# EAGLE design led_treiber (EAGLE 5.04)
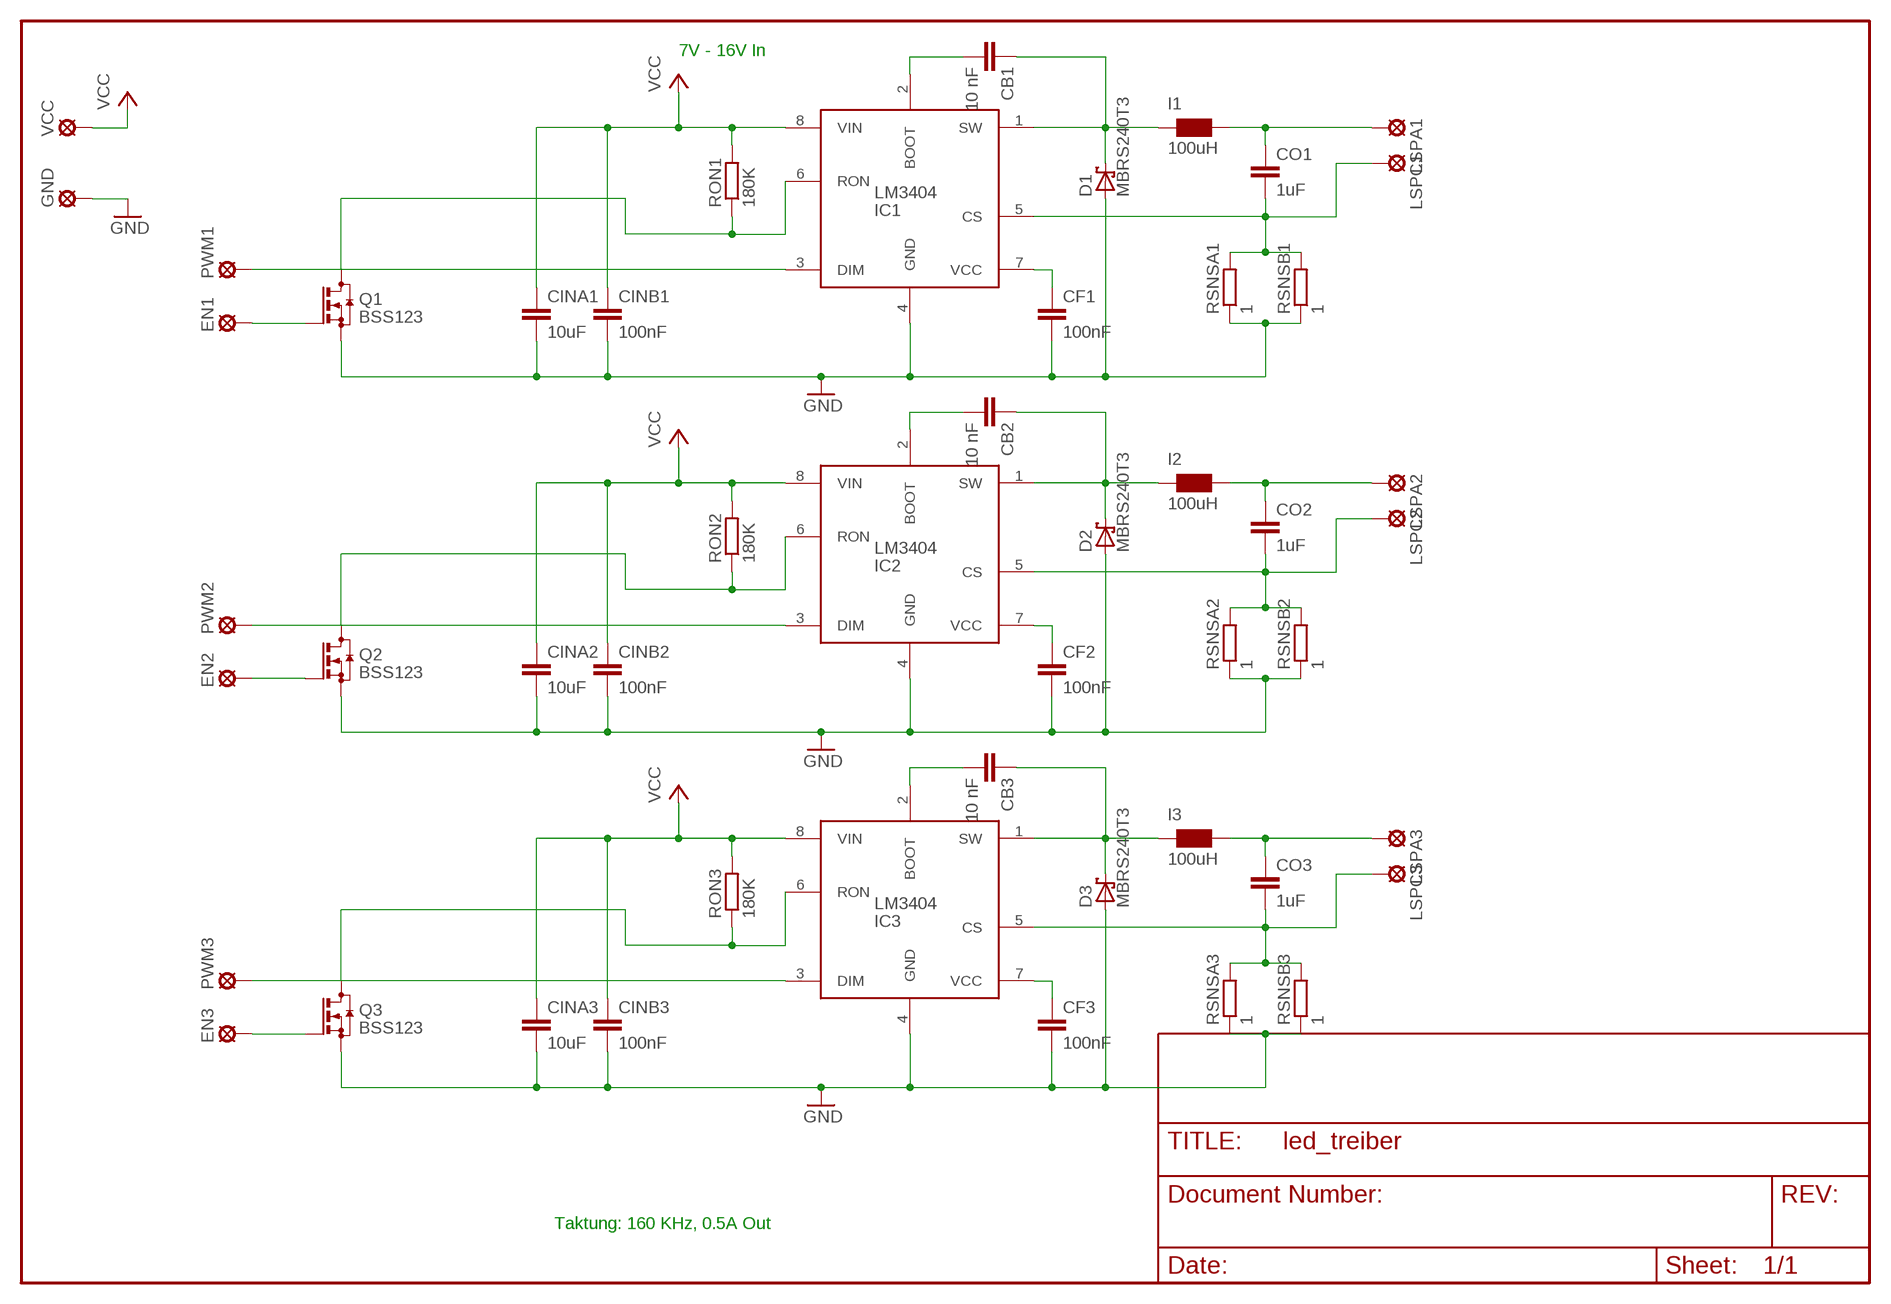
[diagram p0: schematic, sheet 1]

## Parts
CB1  10 nF  C-EUC0805  [C0805]
CB2  10 nF  C-EUC0805  [C0805]
CB3  10 nF  C-EUC0805  [C0805]
CF1  100nF  C-EUC0805  [C0805]
CF2  100nF  C-EUC0805  [C0805]
CF3  100nF  C-EUC0805  [C0805]
CINA1  10uF  C-EUC1210  [C1210]
CINA2  10uF  C-EUC1210  [C1210]
CINA3  10uF  C-EUC1210  [C1210]
CINB1  100nF  C-EUC0805  [C0805]
CINB2  100nF  C-EUC0805  [C0805]
CINB3  100nF  C-EUC0805  [C0805]
CO1  1uF  C-EUC1210  [C1210]
CO2  1uF  C-EUC1210  [C1210]
CO3  1uF  C-EUC1210  [C1210]
D1  MBRS240T3  MBRS130LT3  [SMB]
D2  MBRS240T3  MBRS130LT3  [SMB]
D3  MBRS240T3  MBRS130LT3  [SMB]
EN1  LSP10  [LSP10]
EN2  LSP10  [LSP10]
EN3  LSP10  [LSP10]
GND  LSP10  [LSP10]
I1  100uH  WE-PD_L/XL/XXL  [WE-PD_L/XL/XXL]
I2  100uH  WE-PD_L/XL/XXL  [WE-PD_L/XL/XXL]
I3  100uH  WE-PD_L/XL/XXL  [WE-PD_L/XL/XXL]
IC1  LM3404  [SO-8]
IC2  LM3404  [SO-8]
IC3  LM3404  [SO-8]
LSPA1  LSP10  [LSP10]
LSPA2  LSP10  [LSP10]
LSPA3  LSP10  [LSP10]
LSPC1  LSP10  [LSP10]
LSPC2  LSP10  [LSP10]
LSPC3  LSP10  [LSP10]
PWM1  LSP10  [LSP10]
PWM2  LSP10  [LSP10]
PWM3  LSP10  [LSP10]
Q1  BSS123  [SOT23]
Q2  BSS123  [SOT23]
Q3  BSS123  [SOT23]
RON1  180K  R-EU_R0805  [R0805]
RON2  180K  R-EU_R0805  [R0805]
RON3  180K  R-EU_R0805  [R0805]
RSNSA1  1  R-EU_R0805  [R0805]
RSNSA2  1  R-EU_R0805  [R0805]
RSNSA3  1  R-EU_R0805  [R0805]
RSNSB1  1  R-EU_R0805  [R0805]
RSNSB2  1  R-EU_R0805  [R0805]
RSNSB3  1  R-EU_R0805  [R0805]
VCC  LSP10  [LSP10]

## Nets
ANODE1: CO1.1 I1.1 LSPA1.MP
ANODE2: CO2.1 I2.1 LSPA2.MP
ANODE3: CO3.1 I3.1 LSPA3.MP
BOOT1: CB1.2 IC1.2(BOOT)
BOOT2: CB2.2 IC2.2(BOOT)
BOOT3: CB3.2 IC3.2(BOOT)
CATHODE1: CO1.2 IC1.5(CS) LSPC1.MP RSNSA1.2 RSNSB1.2
CATHODE2: CO2.2 IC2.5(CS) LSPC2.MP RSNSA2.2 RSNSB2.2
CATHODE3: CO3.2 IC3.5(CS) LSPC3.MP RSNSA3.2 RSNSB3.2
CF1: CF1.1 IC1.7(VCC)
CF2: CF2.1 IC2.7(VCC)
CF3: CF3.1 IC3.7(VCC)
ENABLE1: IC1.6(RON) Q1.3(D) RON1.1
ENABLE2: IC2.6(RON) Q2.3(D) RON2.1
ENABLE3: IC3.6(RON) Q3.3(D) RON3.1
ENABLEOUT1: EN1.MP Q1.1(G)
ENABLEOUT2: EN2.MP Q2.1(G)
ENABLEOUT3: EN3.MP Q3.1(G)
GND: CF1.2 CF2.2 CF3.2 CINA1.2 CINA2.2 CINA3.2 CINB1.2 CINB2.2 CINB3.2 D1.A D2.A D3.A GND.MP IC1.4(GND) IC2.4(GND) IC3.4(GND) Q1.2(S) Q2.2(S) Q3.2(S) RSNSA1.1 RSNSA2.1 RSNSA3.1 RSNSB1.1 RSNSB2.1 RSNSB3.1
PWM1: IC1.3(DIM) PWM1.MP
PWM2: IC2.3(DIM) PWM2.MP
PWM3: IC3.3(DIM) PWM3.MP
SW1: CB1.1 D1.C I1.2 IC1.1(SW)
SW2: CB2.1 D2.C I2.2 IC2.1(SW)
SW3: CB3.1 D3.C I3.2 IC3.1(SW)
VCC: CINA1.1 CINA2.1 CINA3.1 CINB1.1 CINB2.1 CINB3.1 IC1.8(VIN) IC2.8(VIN) IC3.8(VIN) RON1.2 RON2.2 RON3.2 VCC.MP

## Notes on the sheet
- 7V - 16V In
- Taktung: 160 KHz, 0.5A Out

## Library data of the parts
CB1-CB3 CF1-CF3 CINA1-CINA3 CINB1-CINB3 CO1-CO3 = rcl:C-EU: CAPACITOR, European symbol
D1-D3 = diode:MBRS130LT3: Schottky Power Rectifier
EN1-EN3 GND LSPA1-LSPA3 LSPC1-LSPC3 PWM1-PWM3 VCC = solpad:LSP10: SOLDER PAD
I1-I3 = wuerth-elektronik:WE-PD: SMD-Shielded Power Inductors WE-PD
IC1-IC3 = lm3404:LM3404
Q1-Q3 = transistor-small-signal:BSS123: N-CHANNEL MOS FET
RON1-RON3 RSNSA1-RSNSA3 RSNSB1-RSNSB3 = rcl:R-EU_: RESISTOR, European symbol

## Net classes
0 default: width 0.635 mm
1 vcc: width 0.254 mm

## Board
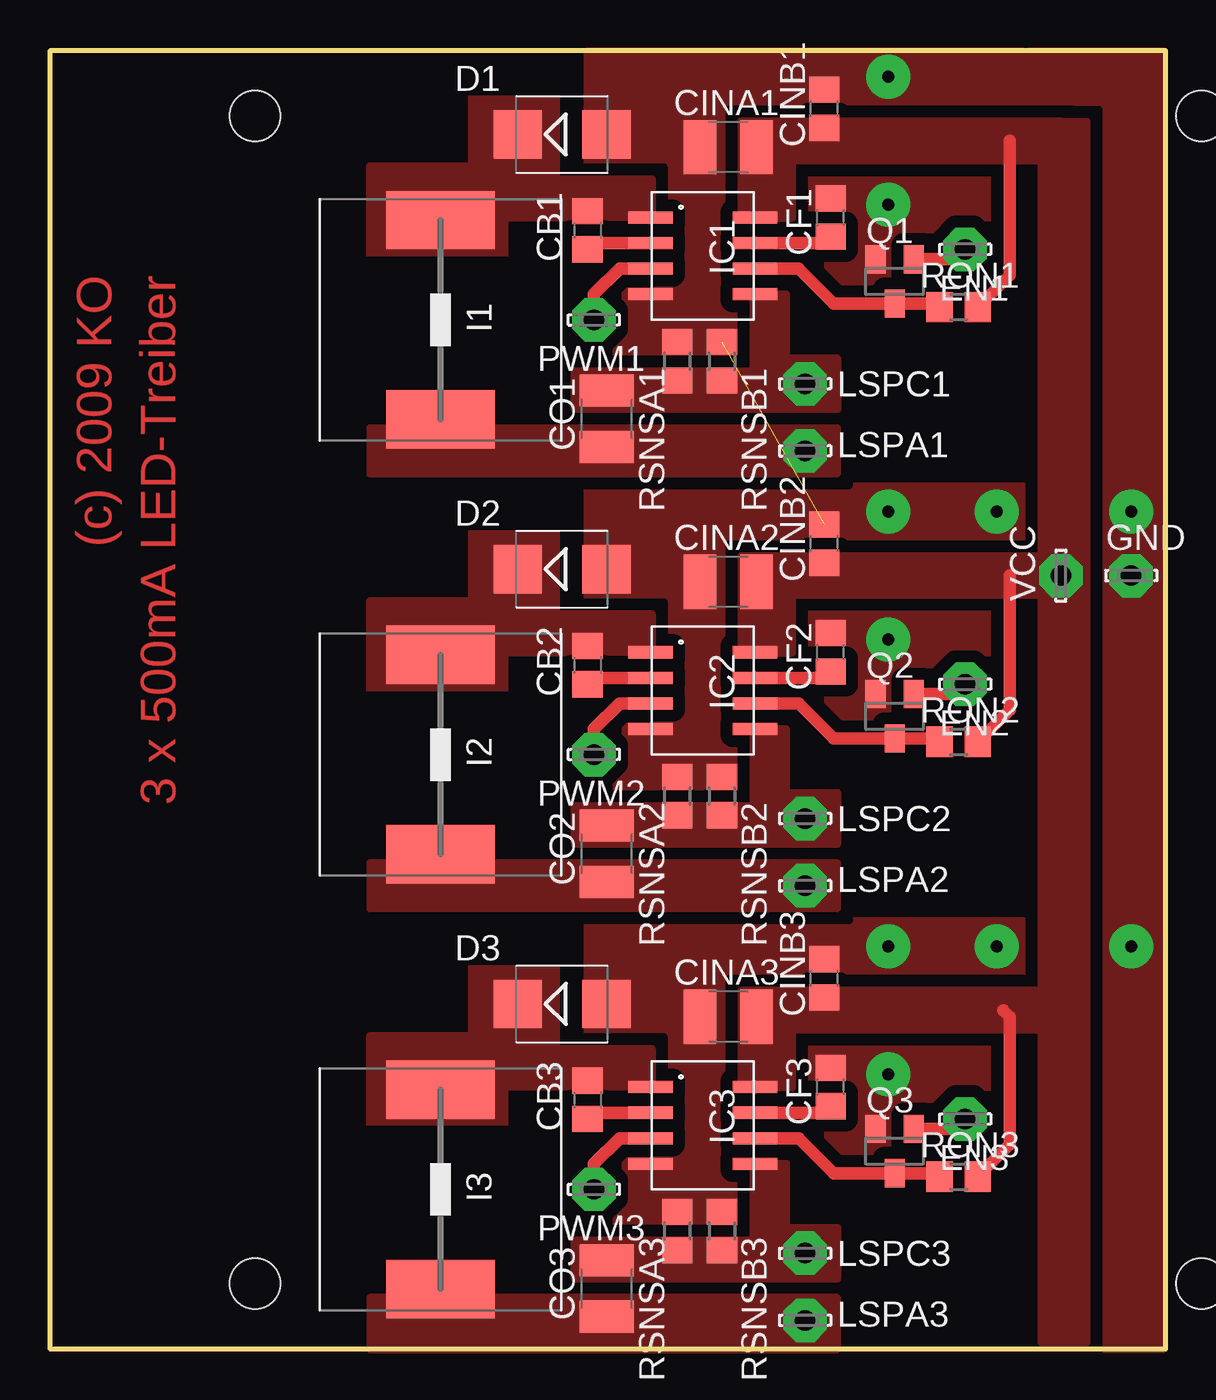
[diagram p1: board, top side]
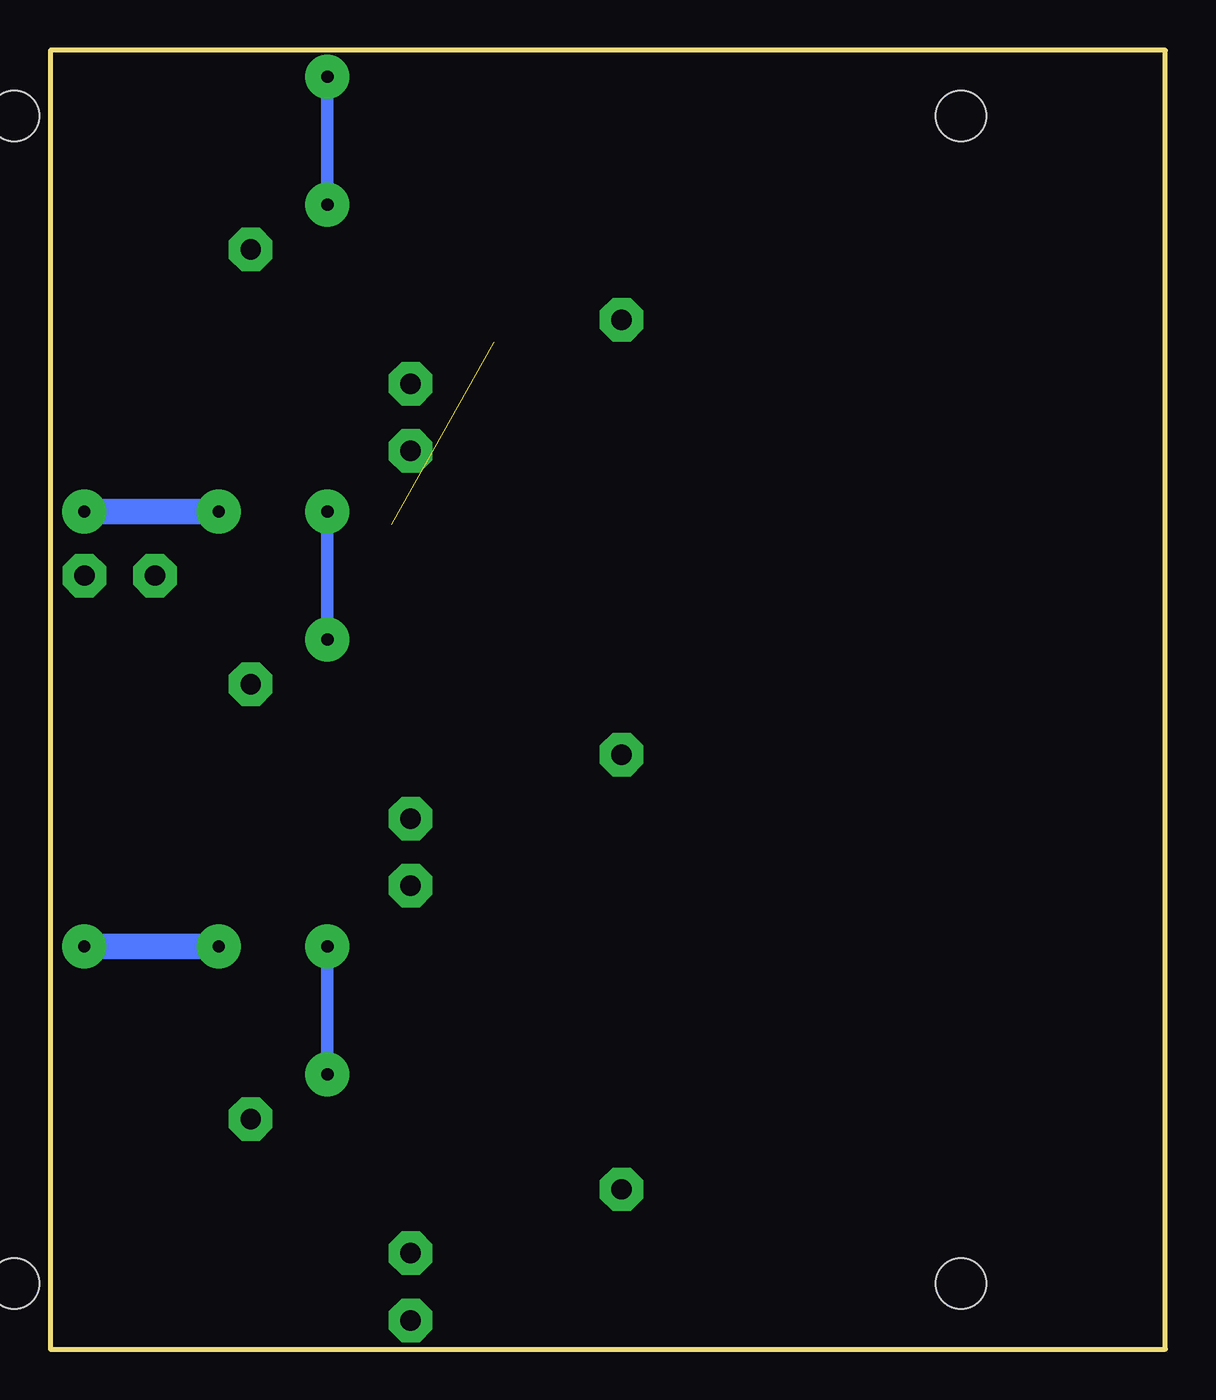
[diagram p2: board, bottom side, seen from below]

Size 55.35 x 64.5 mm. Coordinates in mm from the lower left corner, seen from the top.
Outline: 55.35,64.5 55.35,0 0,0 0,64.5 55.35,64.5
Copper layers (1*16): Top 0.035mm / dielectric 1.5mm / Bottom 0.035mm
Design rules "default *": minimum track width 10mil, minimum drill 24mil, track to track 8mil, track to pad 8mil, pad to pad 8mil, via to via 8mil, smd to smd 8mil, copper to edge 0mil, drill to drill 8mil, minimum pad ring 10mil, minimum via ring 8mil, stop-mask expansion 4mil, vias tented up to drill 0mil, thermal gap 10mil
Holes 2.5 mm at 10.15,61.25 57.15,61.25 57.15,3.25 10.15,3.25
tRestrict: area 10.2,43.2 to 25.7,64.5; area 10.2,21.6 to 25.7,42.2; area 10.2,0 to 25.7,20.6

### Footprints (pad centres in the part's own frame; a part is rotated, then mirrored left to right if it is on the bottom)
C0805 = smd 1.3 x 1.5: 1 -0.95,0; 2 0.95,0
C1210 = smd 1.6 x 2.7: 1 -1.4,0; 2 1.4,0
SMB = smd 2.4 x 2.4: A 2.2,0; C -2.2,0
LSP10 = drill 1.016 pad 2.159 octagon: MP 0,0
WE-PD_L/XL/XXL = smd 2.9 x 5.4: 1 -4.95,0; 2 4.95,0
SO-8 = smd 2.2 x 0.6: 1 -2.6,2.54; 2 -2.6,1.27; 3 -2.6,0; 4 -2.6,-1.27; 5 2.6,-1.27; 6 2.6,0; 7 2.6,1.27; 8 2.6,2.54
SOT23 = smd 1 x 1.4: 1 -0.95,-1.1; 2 0.95,-1.1; 3 0,1.1
R0805 = smd 1.3 x 1.5: 1 -0.95,0; 2 0.95,0

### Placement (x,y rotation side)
CB1  26.67,55.56 270 top
CB2  26.67,33.97 270 top
CB3  26.67,12.38 270 top
CF1  38.73,56.2 90 top
CF2  38.73,34.61 90 top
CF3  38.73,13.02 90 top
CINA1  33.66,59.69 180 top
CINA2  33.66,38.1 180 top
CINA3  33.66,16.51 180 top
CINB1  38.42,61.59 90 top
CINB2  38.42,40.01 90 top
CINB3  38.42,18.41 90 top
CO1  27.62,46.2 90 top
CO2  27.62,24.61 90 top
CO3  27.62,3.02 90 top
D1  25.4,60.33 0 top
D2  25.4,38.73 0 top
D3  25.4,17.14 0 top
EN1  45.4,54.61 0 top
EN2  45.4,33.02 0 top
EN3  45.4,11.43 0 top
GND  53.66,38.42 0 top
I1  19.37,51.12 90 top
I2  19.37,29.53 90 top
I3  19.37,7.94 90 top
IC1  32.38,53.66 0 top
IC2  32.38,32.07 0 top
IC3  32.38,10.48 0 top
LSPA1  37.47,44.61 0 top
LSPA2  37.47,23.02 0 top
LSPA3  37.47,1.43 0 top
LSPC1  37.47,47.94 0 top
LSPC2  37.47,26.35 0 top
LSPC3  37.47,4.76 0 top
PWM1  26.99,51.12 180 top
PWM2  26.99,29.53 180 top
PWM3  26.99,7.94 180 top
Q1  41.91,53.02 180 top
Q2  41.91,31.43 180 top
Q3  41.91,9.84 180 top
RON1  45.09,51.75 0 top
RON2  45.09,30.16 0 top
RON3  45.09,8.57 0 top
RSNSA1  31.11,49.05 270 top
RSNSA2  31.11,27.46 270 top
RSNSA3  31.11,5.87 270 top
RSNSB1  33.34,49.05 270 top
RSNSB2  33.34,27.46 270 top
RSNSB3  33.34,5.87 270 top
VCC  50.16,38.42 90 top

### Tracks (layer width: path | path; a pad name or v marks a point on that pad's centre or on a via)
ANODE1
  pour Top (isolate 0.61, no thermals): 39.05,43.5 39.05,45.72 24.13,45.72 15.88,45.72 15.88,43.5
ANODE2
  pour Top (isolate 0.61, no thermals): 39.05,21.91 39.05,24.13 24.13,24.13 15.88,24.13 15.88,21.91
ANODE3
  pour Top (isolate 0.61, no thermals): 39.05,0 39.05,2.54 24.13,2.54 15.88,2.54 15.88,0
BOOT1
  Top 0.61: IC1.2 26.67,54.93 CB1.2
  Top 0.635: IC1.2 29.84,54.93
BOOT2
  Top 0.61: IC2.2 26.67,33.34 CB2.2
  Top 0.635: IC2.2 29.84,33.34
BOOT3
  Top 0.61: IC3.2 26.67,11.75 CB3.2
  Top 0.635: IC3.2 29.84,11.75
CATHODE1
  pour Top (no thermals): 34.92,52.39 36.51,52.39 36.51,49.21 39.05,49.21 39.05,46.67 26.04,46.67 26.04,48.58 34.92,48.58
CATHODE2
  pour Top (no thermals): 34.92,30.8 36.51,30.8 36.51,27.62 39.05,27.62 39.05,25.08 26.04,25.08 26.04,26.99 34.92,26.99
CATHODE3
  pour Top (no thermals): 34.92,9.21 36.51,9.21 36.51,6.03 39.05,6.03 39.05,3.49 26.04,3.49 26.04,5.4 34.92,5.4
CF1
  Top 0.61: IC1.7 39.05,54.93 CF1.1
  Top 0.635: IC1.7 34.92,54.93
CF2
  Top 0.61: IC2.7 39.05,33.34 CF2.1
  Top 0.635: IC2.7 34.92,33.34
CF3
  Top 0.61: IC3.7 39.05,11.75 CF3.1
  Top 0.635: IC3.7 34.92,11.75
ENABLE1
  Top 0.61: IC1.6 37.15,53.66 38.88,51.92 Q1.3 43.97,51.92 RON1.1
ENABLE2
  Top 0.61: RON2.1 43.97,30.33 Q2.3 38.88,30.33 37.15,32.07 IC2.6
ENABLE3
  Top 0.61: RON3.1 43.97,8.74 Q3.3 38.88,8.74 37.15,10.48 IC3.6
ENABLEOUT1
  Top 0.61: Q1.1 44.91,54.12 EN1.MP
ENABLEOUT2
  Top 0.61: Q2.1 44.91,32.53 EN2.MP
ENABLEOUT3
  Top 0.61: Q3.1 44.91,10.94 EN3.MP
GND  (via drill 0.6 pad 2.18)  (1 unrouted)
  Bottom 0.61: v41.59,56.83 v41.59,63.18 | v41.59,35.24 v41.59,41.59 | v41.59,13.65 v41.59,20
  Bottom 1.27: v46.99,41.59 v53.66,41.59 | v46.99,20 v53.66,20
  pour Top (isolate 0.61, rank 2, no thermals): 48.26,43.18 26.67,43.18 26.67,64.45 48.26,64.45
  pour Top (isolate 0.61, rank 2, no thermals): 48.58,64.45 55.24,64.45 55.24,0 48.58,0
  pour Top (isolate 0.61, rank 2, no thermals): 48.26,21.59 26.67,21.91 26.67,42.86 48.26,42.86
  pour Top (isolate 0.61, rank 2, no thermals): 48.26,0 26.67,0.32 26.67,21.27 48.26,21.27
PWM1
  Top 0.61: IC1.3 28.26,53.66 26.99,52.39 PWM1.MP
PWM2
  Top 0.61: IC2.3 28.26,32.07 26.99,30.8 PWM2.MP
PWM3
  Top 0.61: IC3.3 28.26,10.48 26.99,9.21 PWM3.MP
SW1
  Top 0.635: IC1.1 29.84,56.2
  pour Top (isolate 0.813, no thermals): 29.84,56.2 22.54,56.2 22.54,54.29 15.88,54.29 15.88,58.74 20.95,58.74 20.95,62.55 25.08,62.55 25.08,58.1 29.84,58.1
SW2
  Top 0.635: IC2.1 29.84,34.61
  pour Top (isolate 0.813, no thermals): 29.84,34.61 22.54,34.61 22.54,32.7 15.88,32.7 15.88,37.15 20.95,37.15 20.95,40.96 25.08,40.96 25.08,36.51 29.84,36.51
SW3
  Top 0.635: IC3.1 29.84,13.02
  pour Top (isolate 0.813, no thermals): 29.84,13.02 22.54,13.02 22.54,11.11 15.88,11.11 15.88,15.56 20.95,15.56 20.95,19.37 25.08,19.37 25.08,14.92 29.84,14.92
VCC
  Top 0.61: RON2.2 47.62,31.75 47.62,38.42 | 47.31,16.83 47.62,16.51 47.62,10.16 RON3.2 | RON1.2 47.62,53.34 47.62,60.01
  Top 0.635: IC1.8 34.92,56.2 | IC3.8 34.92,13.02 | IC2.8 34.92,34.61
  pour Top (isolate 0.61, no thermals): 51.44,0.32 49.21,0.32 49.21,60.96 51.44,60.96
  pour Top (isolate 0.61, no thermals): 50.16,60.96 34.29,60.96 34.29,56.2 36.83,56.2 36.83,59.05 50.16,59.05
  pour Top (isolate 0.61, no thermals): 50.16,39.37 34.29,39.37 34.29,34.61 36.83,34.61 36.83,37.47 50.16,37.47
  pour Top (isolate 0.61, no thermals): 50.16,17.78 34.29,17.78 34.29,13.02 36.83,13.02 36.83,15.88 50.16,15.88

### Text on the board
Top: (c) 2009 KO | 3 x 500mA LED-Treiber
